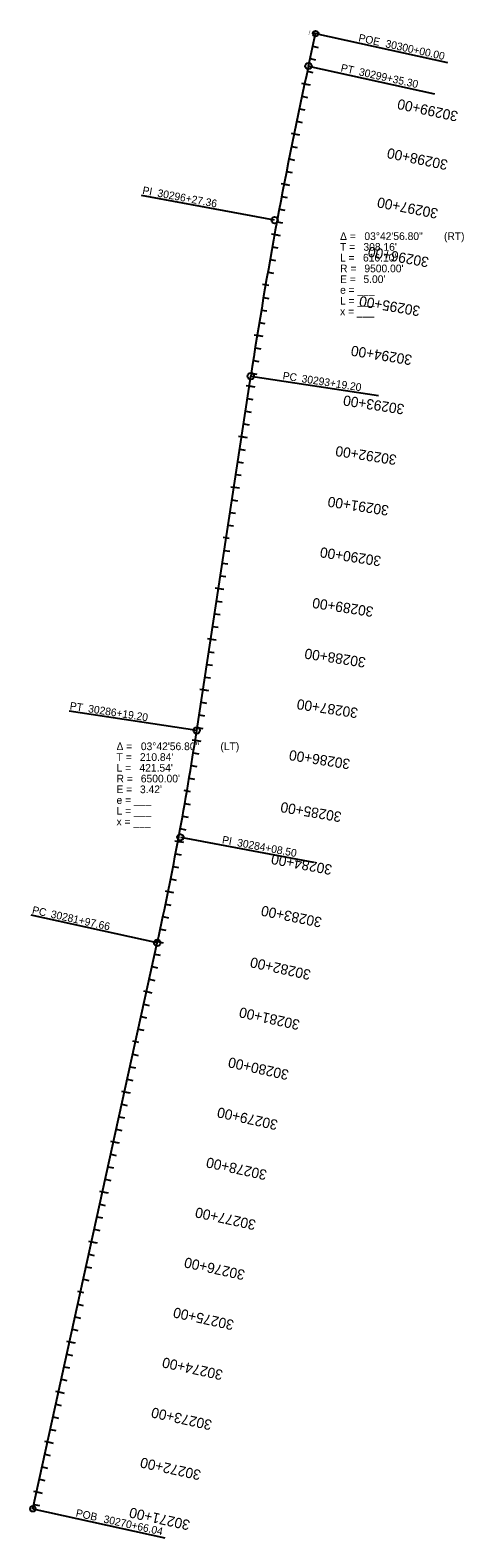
# Model space of a CAD drawing. Extents: x 14107572 to 14108419, y 8638022 to 8640965.
import ezdxf

# ---------------------------------------------------------------- set-up
doc = ezdxf.new("R2010")
doc.units = 0
for name, color, linetype in [('_CIVIL_CONSTRUCTION', 7, 'Continuous'), ('Default', 7, 'Continuous'), ('Profile', 7, 'Continuous'), ('Terrain', 7, 'Continuous'), ('TL_DNC', 7, 'Continuous')]:
    doc.layers.add(name, color=color, linetype=linetype)

msp = doc.modelspace()

# ---------------------------------------------------------------- linework, layer by layer
at = {"layer": '_CIVIL_CONSTRUCTION'}
for p, q in [((14108115.4, 8640895.4), (14108129.3, 8640958.6)), ((14107897.2, 8639597.8), (14108002.8, 8640289.8)), ((14107897.2, 8639597.8), (14108002.8, 8640289.8)), ((14107577.4, 8638078.2), (14107820.2, 8639183.4))]:
    msp.add_line(p, q, dxfattribs=at)
for centre, radius, start, end in [((14117394.1, 8638857.1), 9500, 167.61021, 171.32599), ((14117394.1, 8638857.1), 9500, 167.61021, 171.32599), ((14101471.6, 8640578.1), 6500, 347.61021, 351.32599), ((14101471.6, 8640578.1), 6500, 347.61021, 351.32599)]:
    msp.add_arc(centre, radius, start, end, dxfattribs=at)
at = {"layer": 'Default'}
msp.add_line((14108132.3, 8640958), (14108126.3, 8640959.3), dxfattribs=at)
at = {"layer": 'Profile'}
for p, q in [((14108129.3, 8640958.6), (14108387.1, 8640902)), ((14108115.4, 8640895.4), (14108361.5, 8640841.3)), ((14108387.1, 8640902), (14108387.1, 8640902)), ((14108361.5, 8640841.3), (14108361.5, 8640841.3)), ((14108049.3, 8640594.4), (14107789.7, 8640642.7)), ((14107789.7, 8640642.7), (14107789.7, 8640642.7)), ((14108002.8, 8640289.8), (14108251.9, 8640251.8)), ((14108251.9, 8640251.8), (14108251.9, 8640251.8)), ((14107897.2, 8639597.8), (14107648.1, 8639635.8)), ((14107648.1, 8639635.8), (14107648.1, 8639635.8)), ((14107865.4, 8639389.4), (14108125, 8639341.1)), ((14108125, 8639341.1), (14108125, 8639341.1)), ((14107820.2, 8639183.4), (14107574.1, 8639237.5)), ((14107574.1, 8639237.5), (14107574.1, 8639237.5)), ((14107577.4, 8638078.2), (14107835.2, 8638021.5)), ((14107835.2, 8638021.5), (14107835.2, 8638021.5))]:
    msp.add_line(p, q, dxfattribs=at)
for centre, radius in [((14108129.3, 8640958.6), 5.34), ((14108115.4, 8640895.4), 6.24), ((14108049.3, 8640594.4), 6.24), ((14108002.8, 8640289.8), 6.24), ((14107897.2, 8639597.8), 6.24), ((14107865.4, 8639389.4), 6.24), ((14107820.2, 8639183.4), 6.24), ((14107577.4, 8638078.2), 5.34)]:
    msp.add_circle(centre, radius, dxfattribs=at)
at = {"layer": 'Terrain'}
for p, q in [((14108107.9, 8640860.9), (14108118.6, 8640858.6)), ((14108087.3, 8640763.1), (14108098, 8640760.9)), ((14108067.8, 8640665), (14108078.5, 8640662.9)), ((14108049.2, 8640566.7), (14108060, 8640564.8)), ((14108025.7, 8640469.3), (14108037.8, 8640467.2)), ((14108015.3, 8640369.6), (14108026.1, 8640367.9)), ((14107999.9, 8640270.8), (14108010.7, 8640269.2)), ((14107984.8, 8640172), (14107995.6, 8640170.3)), ((14107969.7, 8640073.1), (14107980.5, 8640071.5)), ((14107948.6, 8639975.2), (14107960.7, 8639973.3)), ((14107939.6, 8639875.4), (14107950.4, 8639873.7)), ((14107924.5, 8639776.5), (14107935.3, 8639774.9)), ((14107909.4, 8639677.7), (14107920.2, 8639676)), ((14107894.3, 8639578.8), (14107905.1, 8639577.2)), ((14107872.1, 8639481.2), (14107884.2, 8639479.1)), ((14107860.5, 8639381.7), (14107871.3, 8639379.7)), ((14107841.4, 8639283.6), (14107852.1, 8639281.4)), ((14107820.7, 8639185.7), (14107831.4, 8639183.4)), ((14107799.2, 8639088.1), (14107809.9, 8639085.7)), ((14107771.8, 8638991.7), (14107783.8, 8638989.1)), ((14107756.3, 8638892.7), (14107767, 8638890.4)), ((14107734.9, 8638795), (14107745.5, 8638792.7)), ((14107713.4, 8638697.4), (14107724.1, 8638695)), ((14107692, 8638599.7), (14107702.6, 8638597.4)), ((14107664.5, 8638503.3), (14107676.5, 8638500.7)), ((14107649, 8638404.4), (14107659.7, 8638402)), ((14107627.6, 8638306.7), (14107638.3, 8638304.3)), ((14107606.1, 8638209), (14107616.8, 8638206.7)), ((14107584.7, 8638111.3), (14107595.3, 8638109))]:
    msp.add_line(p, q, dxfattribs=at)
at = {"layer": 'TL_DNC'}
for p, q in [((14108123.9, 8640934.2), (14108134.6, 8640931.8)), ((14108118.5, 8640909.8), (14108129.2, 8640907.4)), ((14108101.9, 8640862.2), (14108113.9, 8640859.6)), ((14108113.2, 8640885.4), (14108123.9, 8640883)), ((14108102.6, 8640836.5), (14108113.3, 8640834.2)), ((14108097.5, 8640812), (14108108.2, 8640809.8)), ((14108092.4, 8640787.5), (14108103, 8640785.3)), ((14108081.3, 8640764.3), (14108093.3, 8640761.8)), ((14108077.4, 8640714.1), (14108088.1, 8640711.9)), ((14108082.3, 8640738.6), (14108093, 8640736.4)), ((14108072.5, 8640689.5), (14108083.3, 8640687.4)), ((14108061.8, 8640666.2), (14108073.8, 8640663.8)), ((14108063, 8640640.4), (14108073.8, 8640638.4)), ((14108058.4, 8640615.9), (14108069.1, 8640613.9)), ((14108043.2, 8640567.8), (14108055.3, 8640565.6)), ((14108053.8, 8640591.3), (14108064.5, 8640589.3)), ((14108044.8, 8640542.1), (14108055.5, 8640540.2)), ((14108040.4, 8640517.5), (14108051.1, 8640515.6)), ((14108036, 8640492.9), (14108046.8, 8640491)), ((14108025.7, 8640469.3), (14108037.8, 8640467.2)), ((14108027.6, 8640443.6), (14108038.3, 8640441.8)), ((14108019.3, 8640394.3), (14108030.1, 8640392.5)), ((14108023.4, 8640419), (14108034.2, 8640417.2)), ((14108009.3, 8640370.6), (14108021.4, 8640368.6)), ((14108011.4, 8640344.9), (14108022.2, 8640343.2)), ((14108007.5, 8640320.2), (14108018.3, 8640318.6)), ((14108003.7, 8640295.5), (14108014.5, 8640293.9)), ((14107993.9, 8640271.7), (14108006, 8640269.9)), ((14107996.1, 8640246.1), (14108006.9, 8640244.5)), ((14107992.4, 8640221.4), (14108003.2, 8640219.7)), ((14107988.6, 8640196.7), (14107999.4, 8640195)), ((14107978.8, 8640172.9), (14107990.9, 8640171)), ((14107981.1, 8640147.2), (14107991.8, 8640145.6)), ((14107973.5, 8640097.8), (14107984.3, 8640096.2)), ((14107977.3, 8640122.5), (14107988.1, 8640120.9)), ((14107963.7, 8640074), (14107975.8, 8640072.2)), ((14107966, 8640048.4), (14107976.8, 8640046.7)), ((14107962.2, 8640023.7), (14107973, 8640022)), ((14107958.4, 8639999), (14107969.2, 8639997.3)), ((14107948.6, 8639975.2), (14107960.7, 8639973.3)), ((14107950.9, 8639949.5), (14107961.7, 8639947.9)), ((14107947.1, 8639924.8), (14107957.9, 8639923.2)), ((14107943.4, 8639900.1), (14107954.1, 8639898.5)), ((14107933.5, 8639876.3), (14107945.6, 8639874.5)), ((14107935.8, 8639850.7), (14107946.6, 8639849)), ((14107928.3, 8639801.3), (14107939.1, 8639799.6)), ((14107932, 8639826), (14107942.8, 8639824.3)), ((14107918.4, 8639777.5), (14107930.5, 8639775.6)), ((14107920.7, 8639751.8), (14107931.5, 8639750.2)), ((14107917, 8639727.1), (14107927.8, 8639725.5)), ((14107913.2, 8639702.4), (14107924, 8639700.7)), ((14107903.4, 8639678.6), (14107915.5, 8639676.8)), ((14107901.9, 8639628.3), (14107912.7, 8639626.6)), ((14107905.6, 8639653), (14107916.4, 8639651.3)), ((14107898.1, 8639603.5), (14107908.9, 8639601.9)), ((14107888.3, 8639579.8), (14107900.4, 8639577.9)), ((14107890.4, 8639554.1), (14107901.2, 8639552.4)), ((14107886.4, 8639529.5), (14107897.2, 8639527.7)), ((14107872.1, 8639481.2), (14107884.2, 8639479.1)), ((14107882.4, 8639504.8), (14107893.1, 8639503)), ((14107873.9, 8639455.5), (14107884.7, 8639453.6)), ((14107869.5, 8639430.9), (14107880.3, 8639429)), ((14107865.1, 8639406.3), (14107875.8, 8639404.3)), ((14107854.5, 8639382.8), (14107866.5, 8639380.6)), ((14107851.1, 8639332.6), (14107861.9, 8639330.5)), ((14107855.9, 8639357.1), (14107866.6, 8639355.1)), ((14107846.3, 8639308.1), (14107857, 8639305.9)), ((14107835.4, 8639284.8), (14107847.4, 8639282.3)), ((14107836.3, 8639259.1), (14107847, 8639256.9)), ((14107831.2, 8639234.6), (14107841.9, 8639232.3)), ((14107814.7, 8639187), (14107826.7, 8639184.4)), ((14107826, 8639210.2), (14107836.7, 8639207.9)), ((14107815.3, 8639161.3), (14107826, 8639159)), ((14107810, 8639136.9), (14107820.6, 8639134.5)), ((14107804.6, 8639112.5), (14107815.3, 8639110.1)), ((14107793.3, 8639089.4), (14107805.2, 8639086.7)), ((14107788.5, 8639039.2), (14107799.2, 8639036.9)), ((14107793.9, 8639063.6), (14107804.5, 8639061.3)), ((14107783.1, 8639014.8), (14107793.8, 8639012.5)), ((14107771.8, 8638991.7), (14107783.8, 8638989.1)), ((14107772.4, 8638966), (14107783.1, 8638963.6)), ((14107767.1, 8638941.5), (14107777.7, 8638939.2)), ((14107750.4, 8638894), (14107762.3, 8638891.4)), ((14107761.7, 8638917.1), (14107772.4, 8638914.8)), ((14107751, 8638868.3), (14107761.6, 8638866)), ((14107745.6, 8638843.9), (14107756.3, 8638841.5)), ((14107740.2, 8638819.5), (14107750.9, 8638817.1)), ((14107728.9, 8638796.4), (14107740.9, 8638793.7)), ((14107724.1, 8638746.2), (14107734.8, 8638743.9)), ((14107729.5, 8638770.6), (14107740.2, 8638768.3)), ((14107718.8, 8638721.8), (14107729.4, 8638719.4)), ((14107707.4, 8638698.7), (14107719.4, 8638696.1)), ((14107708.1, 8638673), (14107718.7, 8638670.6)), ((14107697.3, 8638624.1), (14107708, 8638621.8)), ((14107702.7, 8638648.5), (14107713.4, 8638646.2)), ((14107686, 8638601), (14107697.9, 8638598.4)), ((14107686.6, 8638575.3), (14107697.3, 8638572.9)), ((14107681.2, 8638550.9), (14107691.9, 8638548.5)), ((14107675.9, 8638526.4), (14107686.5, 8638524.1)), ((14107664.5, 8638503.3), (14107676.5, 8638500.7)), ((14107665.1, 8638477.6), (14107675.8, 8638475.3)), ((14107659.8, 8638453.2), (14107670.4, 8638450.8)), ((14107654.4, 8638428.8), (14107665.1, 8638426.4)), ((14107643.1, 8638405.7), (14107655, 8638403)), ((14107643.7, 8638379.9), (14107654.4, 8638377.6)), ((14107633, 8638331.1), (14107643.6, 8638328.8)), ((14107638.3, 8638355.5), (14107649, 8638353.2)), ((14107621.6, 8638308), (14107633.6, 8638305.4)), ((14107622.2, 8638282.3), (14107632.9, 8638279.9)), ((14107616.9, 8638257.9), (14107627.5, 8638255.5)), ((14107611.5, 8638233.4), (14107622.2, 8638231.1)), ((14107600.2, 8638210.3), (14107612.1, 8638207.7)), ((14107600.8, 8638184.6), (14107611.4, 8638182.3)), ((14107595.4, 8638160.2), (14107606.1, 8638157.8)), ((14107590, 8638135.8), (14107600.7, 8638133.4)), ((14107578.7, 8638112.7), (14107590.7, 8638110)), ((14107579.3, 8638086.9), (14107590, 8638084.6))]:
    msp.add_line(p, q, dxfattribs=at)

# ---------------------------------------------------------------- texts
at = {"layer": 'Default'}
msp.add_text('300+00', height=2, rotation=77.6102, dxfattribs=at).set_placement((14108117.7, 8640956.4))
at = {"layer": 'Profile'}
for s, rotation, p in [('POE ', 347.6102, (14108212, 8640943.8)), ('30300+00.00', 347.6102, (14108264.6, 8640932.3)), ('PT', 347.6102, (14108177.4, 8640885.2)), ('30299+35.30', 347.6102, (14108212.8, 8640877.4)), ('PI ', 349.4681, (14107790.3, 8640645.9)), ('30296+27.36', 349.4681, (14107819.7, 8640640.5)), ('PC', 351.326, (14108064.3, 8640283.7)), ('30293+19.20', 351.326, (14108101.2, 8640278.1)), ('PT', 351.326, (14107648.6, 8639639.1)), ('30286+19.20', 351.326, (14107684.5, 8639633.6)), ('PI ', 349.4681, (14107945.8, 8639377.8)), ('30284+08.50', 349.4681, (14107975.2, 8639372.3)), ('PC', 347.6102, (14107574.8, 8639240.7)), ('30281+97.66', 347.6102, (14107611.2, 8639232.7)), ('POB ', 347.6102, (14107660.1, 8638063.4)), ('30270+66.04', 347.6102, (14107714.3, 8638051.5))]:
    msp.add_text(s, height=15, rotation=rotation, dxfattribs=at).set_placement(p)
for s, p in [('Δ = ', (14108177.1, 8640555.7)), ('03°42\'56.80"', (14108224.6, 8640555.7)), (' (RT)', (14108374.3, 8640555.7)), ('T = ', (14108177.1, 8640534.7)), ("308.16'", (14108222.7, 8640534.7)), ('L = ', (14108177.1, 8640513.7)), ('R = ', (14108177.1, 8640492.7)), ("616.10'", (14108221.8, 8640513.7)), ("9500.00'", (14108224.5, 8640492.7)), ('E = ', (14108177.1, 8640471.7)), ("5.00'", (14108222.7, 8640471.7)), ('e = ___ ', (14108177.1, 8640450.7)), ('x = ___', (14108177.1, 8640408.7)), ('L = ___', (14108177.1, 8640429.7)), ('Δ = ', (14107740.7, 8639559.6)), ('03°42\'56.80"', (14107788.2, 8639559.6)), (' (LT)', (14107937.9, 8639559.6)), ('T = ', (14107740.7, 8639538.6)), ("210.84'", (14107786.3, 8639538.6)), ('L = ', (14107740.7, 8639517.6)), ('R = ', (14107740.7, 8639496.6)), ("421.54'", (14107785.4, 8639517.6)), ("6500.00'", (14107788.1, 8639496.6)), ('E = ', (14107740.7, 8639475.6)), ("3.42'", (14107786.4, 8639475.6)), ('e = ___ ', (14107740.7, 8639454.6)), ('L = ___', (14107740.7, 8639433.6)), ('x = ___', (14107740.7, 8639412.6))]:
    msp.add_text(s, height=15, dxfattribs=at).set_placement(p)
at = {"layer": 'Terrain'}
for s, rotation, p in [('30295+00', 170.2355, (14108334.7, 8640426.3)), ('30290+00', 171.326, (14108258.3, 8639938.1)), ('30285+00', 170.2753, (14108181.1, 8639438.4)), ('30280+00', 167.6102, (14108078.5, 8638934.6)), ('30275+00', 167.6102, (14107971.2, 8638446.2))]:
    msp.add_text(s, height=20.04, rotation=rotation, dxfattribs=at).set_placement(p)
at = {"layer": 'TL_DNC'}
for s, rotation, p in [('30299+00', 167.8231, (14108408.8, 8640806.2)), ('30298+00', 168.4262, (14108388.8, 8640711.6)), ('30297+00', 169.0293, (14108369.7, 8640616.7)), ('30296+00', 169.6324, (14108351.7, 8640521.6)), ('30295+00', 170.2355, (14108334.7, 8640426.3)), ('30294+00', 170.8387, (14108318.7, 8640330.8)), ('30293+00', 171.326, (14108303.6, 8640234.6)), ('30292+00', 171.326, (14108288.5, 8640135.8)), ('30291+00', 171.326, (14108273.4, 8640036.9)), ('30290+00', 171.326, (14108258.3, 8639938.1)), ('30289+00', 171.326, (14108243.3, 8639839.2)), ('30288+00', 171.326, (14108228.2, 8639740.3)), ('30287+00', 171.326, (14108213.1, 8639641.5)), ('30286+00', 171.1568, (14108197.9, 8639541.7)), ('30285+00', 170.2753, (14108181.1, 8639438.4)), ('30284+00', 169.3938, (14108162.8, 8639335.3)), ('30283+00', 168.5123, (14108142.9, 8639232.5)), ('30282+00', 167.6309, (14108121.4, 8639130)), ('30281+00', 167.6102, (14108099.9, 8639032.3)), ('30280+00', 167.6102, (14108078.5, 8638934.6)), ('30279+00', 167.6102, (14108057, 8638836.9)), ('30278+00', 167.6102, (14108035.6, 8638739.2)), ('30277+00', 167.6102, (14108014.1, 8638641.6)), ('30276+00', 167.6102, (14107992.7, 8638543.9)), ('30275+00', 167.6102, (14107971.2, 8638446.2)), ('30274+00', 167.6102, (14107949.7, 8638348.6)), ('30273+00', 167.6102, (14107928.3, 8638250.9)), ('30272+00', 167.6102, (14107906.8, 8638153.2)), ('30271+00', 167.6102, (14107885.4, 8638055.5))]:
    msp.add_text(s, height=20.04, rotation=rotation, dxfattribs=at).set_placement(p)

doc.saveas('drawing.dxf')
